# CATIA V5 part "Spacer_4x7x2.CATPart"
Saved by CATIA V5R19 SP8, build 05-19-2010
Part number: Spacer 4x7x2
Definition: Spacer 4x7x2
Nomenclature: 72342
Bounding box of the stored display mesh (mm): x 0 to 2, y -3.5 to 3.5, z -3.49 to 3.49
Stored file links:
  D:\Documents\1_Travail\1 - ac-limoges.fr\ac-limoges.fr\Emmanuel Maynard - STI2D_Turgot\1 - IT-I2D\Activités_IT_Première\IT_3_Abris_bus\Maquettes numériques\Abribus_eleve\Spacer_4x7x2.CATPart
  C:\Program Files\Dassault Systemes\B19\win_b64\startup\materials\French\Catalog.CATMaterial
  D:\Documents\1_Travail\2- 2I2D\6 -  Ressources ITEC\Ressources Techniques\0-Maquettes numériques_Composants\Catalogue_Makeblock\Catalog_Makeblock\08_Visserie\Tableentretoiseplastique.xls
  D:\Documents\1_Travail\2- 2I2D\6 -  Ressources ITEC\Ressources Techniques\0-Maquettes numériques_Composants\Catalogue_Makeblock\Catalog_Makeblock\08_Visserie\Tableentretoiseplastique.txt
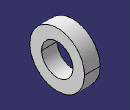
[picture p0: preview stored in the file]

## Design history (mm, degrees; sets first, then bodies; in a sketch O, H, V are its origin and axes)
Parameters
  `Diamètre ext` = 7 mm
  Epaisseur = 2 mm
  `Désignation` = "Spacer 4x7x2"
  `Référence` = "72342"
  `Diamètre int` = 4 mm
AxisSystem1: origin (0, 0, 0), X (1, 0, 0), Y (0, 1, 0), Z (0, 0, 1)
Body1 (main body), material "Aucun"
  Sketch1 on YZ plane of AxisSystem1, origin (0, 0, 0), H (0, 1, 0), V (0, 0, 1)
    circle A1 centre (0, 0) radius 2
    circle A2 centre (0, 0) radius 3.5
    radius A2 = 3.5 {= `Diamètre ext` /2}
    radius A1 = 2 {= `Diamètre int` /2}
  Pad1: profile Sketch1, direction (1, 0, 0), length 2 {= Epaisseur}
